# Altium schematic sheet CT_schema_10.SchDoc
size 281 x 153 mm
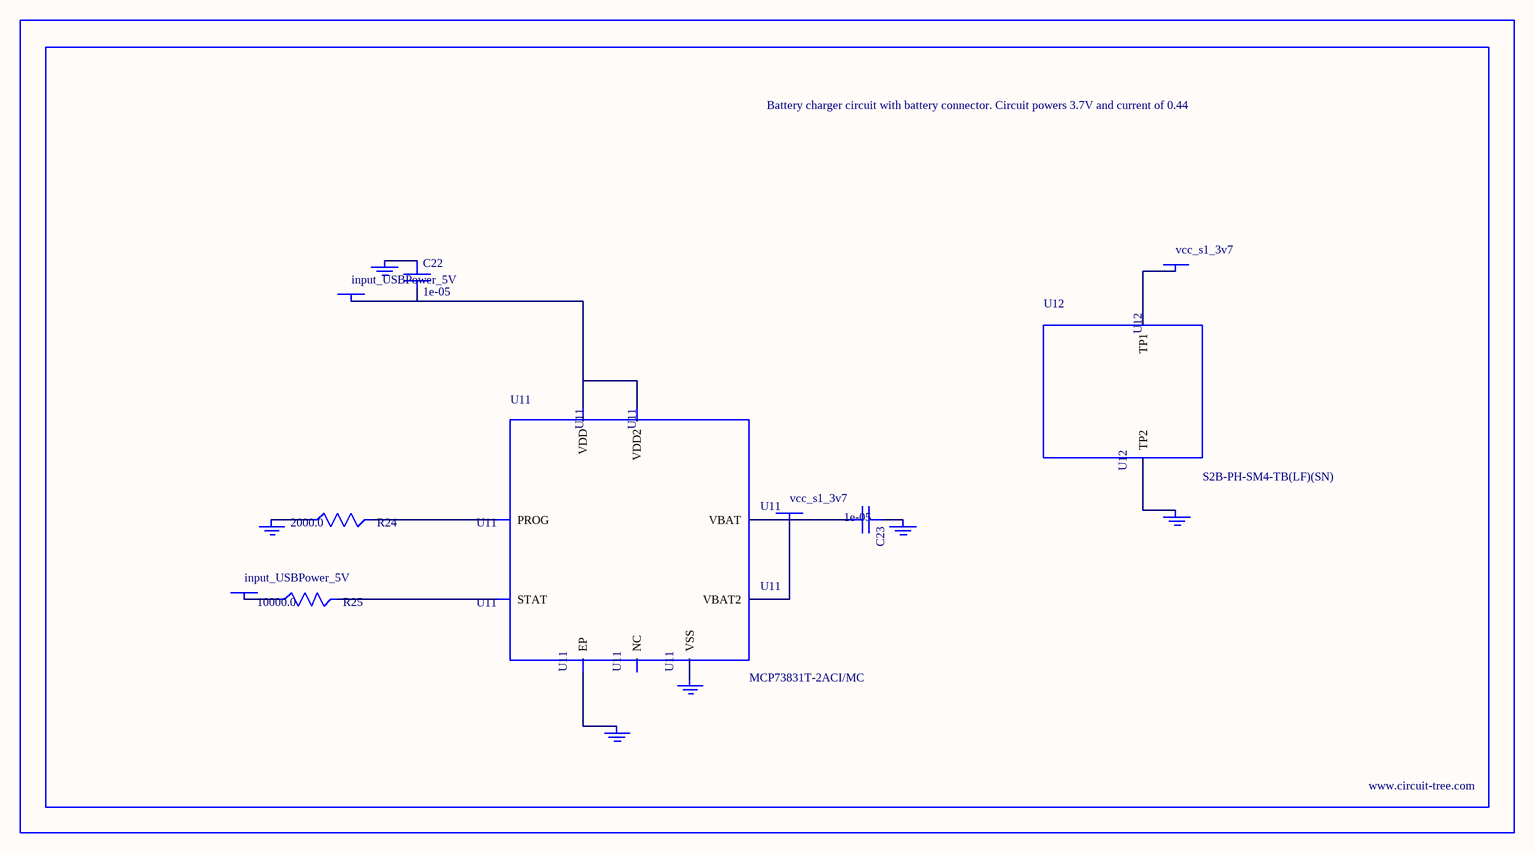
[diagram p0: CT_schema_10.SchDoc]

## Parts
BORDER9  (no value)
C22  1e-05  [C1206]
C23  1e-05  [C1206]
GND_INSTANCE_9_0  (no value)
GND_INSTANCE_9_1  (no value)
GND_INSTANCE_9_2  (no value)
GND_INSTANCE_9_3  (no value)
GND_INSTANCE_9_4  (no value)
GND_INSTANCE_9_5  (no value)
POWER_INSTANCE_9_0  input_USBPower_5V
POWER_INSTANCE_9_1  input_USBPower_5V
POWER_INSTANCE_9_2  vcc_s1_3v7
POWER_INSTANCE_9_3  vcc_s1_3v7
R24  2000.0  [R0603]
R25  10000.0  [R0603]
U11  MCP73831T-2ACI/MC  [DFN8_2X3MC]
U12  S2B-PH-SM4-TB(LF)(SN)  [JST-2-SMD]

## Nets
NetC22_1: C22.1 GND_INSTANCE_9_0.0(GND)
NetC22_2: C22.2 POWER_INSTANCE_9_0.0(PWR) U11.1(VDD) U11.2(VDD2)
NetC23_1: C23.1 GND_INSTANCE_9_1.0(GND)
NetC23_2: C23.2 POWER_INSTANCE_9_2.0(PWR) U11.3(VBAT) U11.4(VBAT2)
NetGND_INSTANCE_9_2_0: GND_INSTANCE_9_2.0(GND) R24.1
NetGND_INSTANCE_9_3_0: GND_INSTANCE_9_3.0(GND) U11.9(EP)
NetGND_INSTANCE_9_4_0: GND_INSTANCE_9_4.0(GND) U11.6(VSS)
NetGND_INSTANCE_9_5_0: GND_INSTANCE_9_5.0(GND) U12.2(TP2)
NetPOWER_INSTANCE_9_1_0: POWER_INSTANCE_9_1.0(PWR) R25.1
NetPOWER_INSTANCE_9_3_0: POWER_INSTANCE_9_3.0(PWR) U12.1(TP1)
NetR24_2: R24.2 U11.8(PROG)
NetR25_2: R25.2 U11.5(STAT)

Not connected (* = marked no-connect by the designer): U11 7(NC)

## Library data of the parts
BORDER9 = BORDER_PAGE9
C22 C23 = C1206C106K3RACTU
GND_INSTANCE_9_0-GND_INSTANCE_9_5 = GND
POWER_INSTANCE_9_0-POWER_INSTANCE_9_3 = PWR
R24 = RC0603JR-072KL
R25 = RC0603JR-0710KL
